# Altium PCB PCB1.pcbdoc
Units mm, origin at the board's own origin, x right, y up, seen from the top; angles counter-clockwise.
Board outline 105.66 x 88.01 mm, 2 copper layers (Top Layer, Bottom Layer), stack 1.58 mm thick; 25 components, 28 nets, 102 pads, 0 vias.
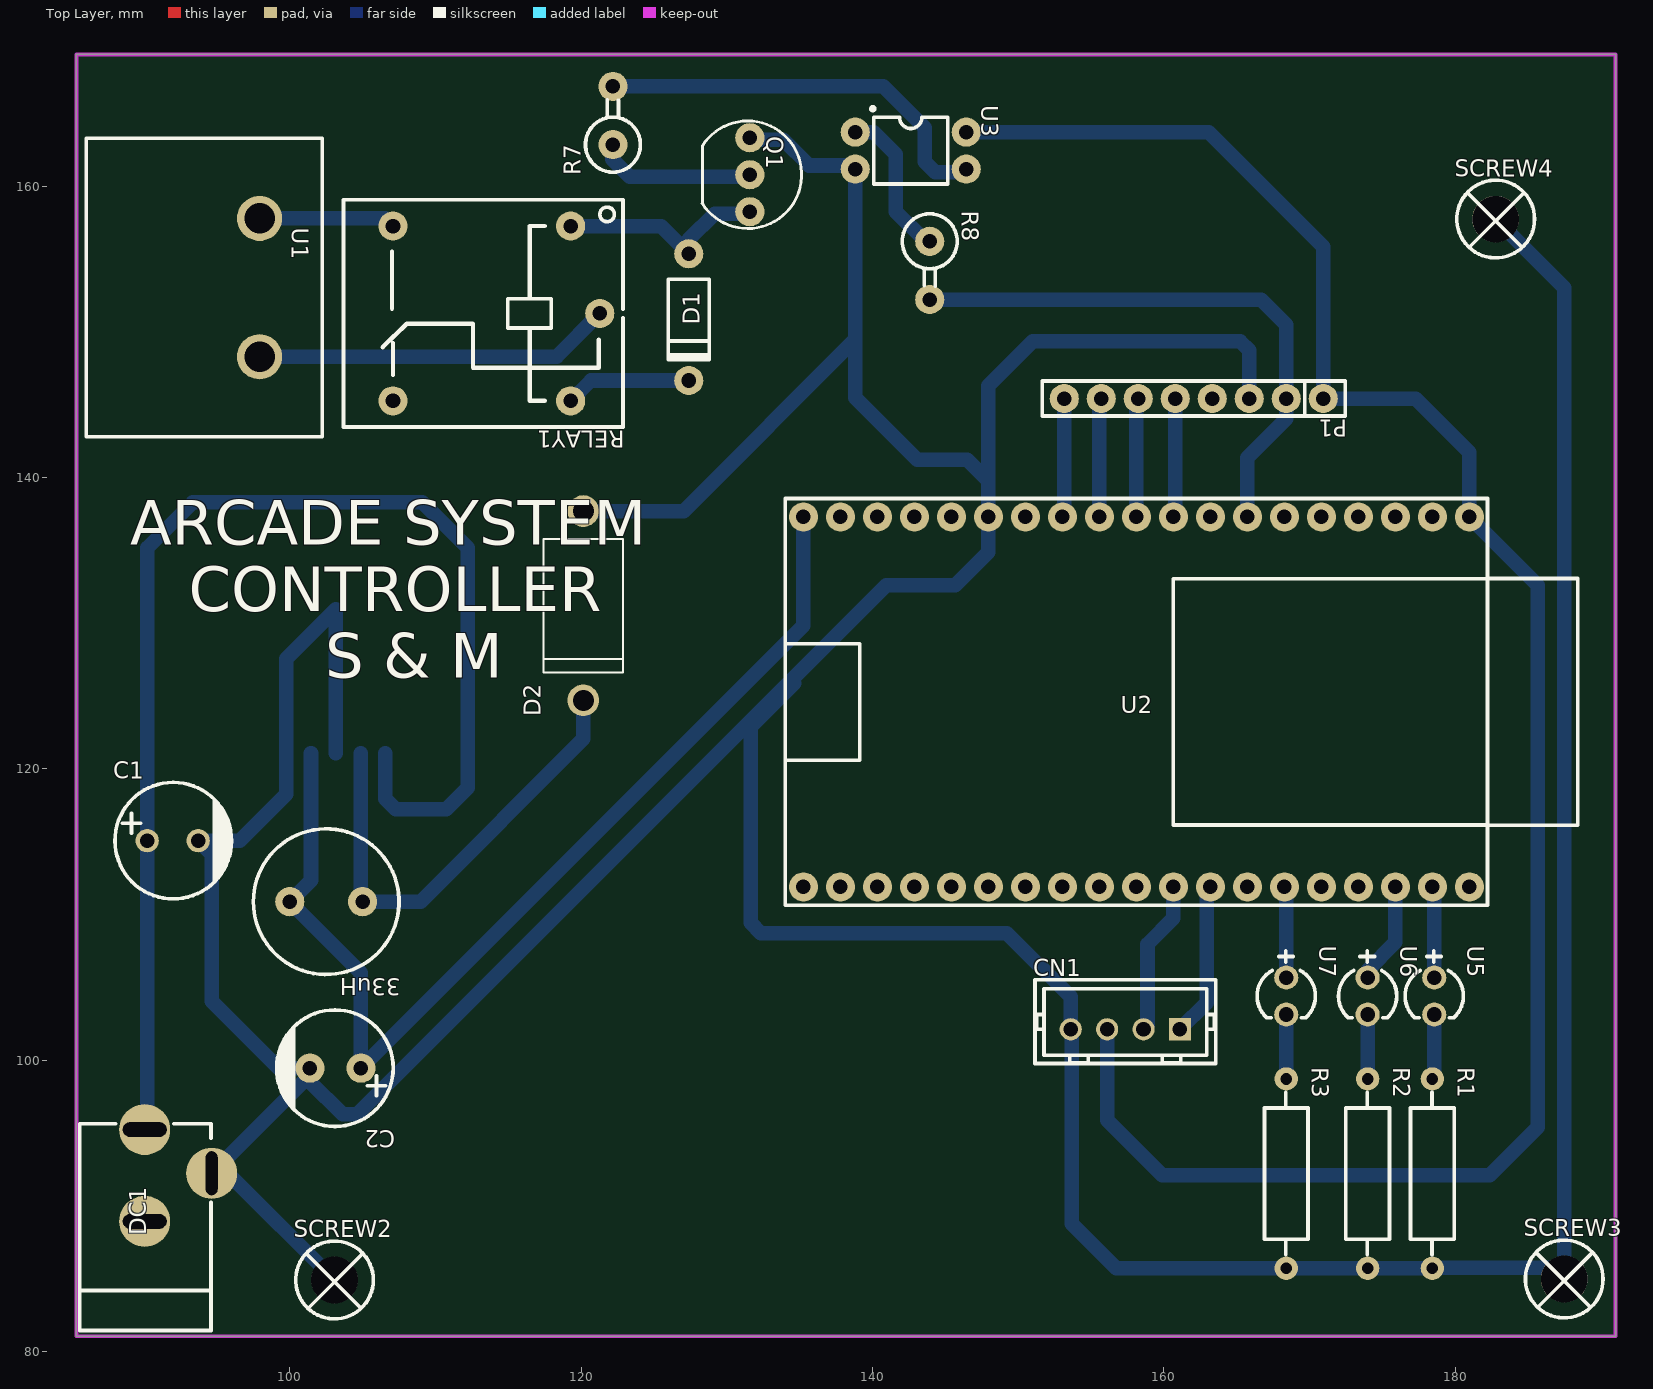
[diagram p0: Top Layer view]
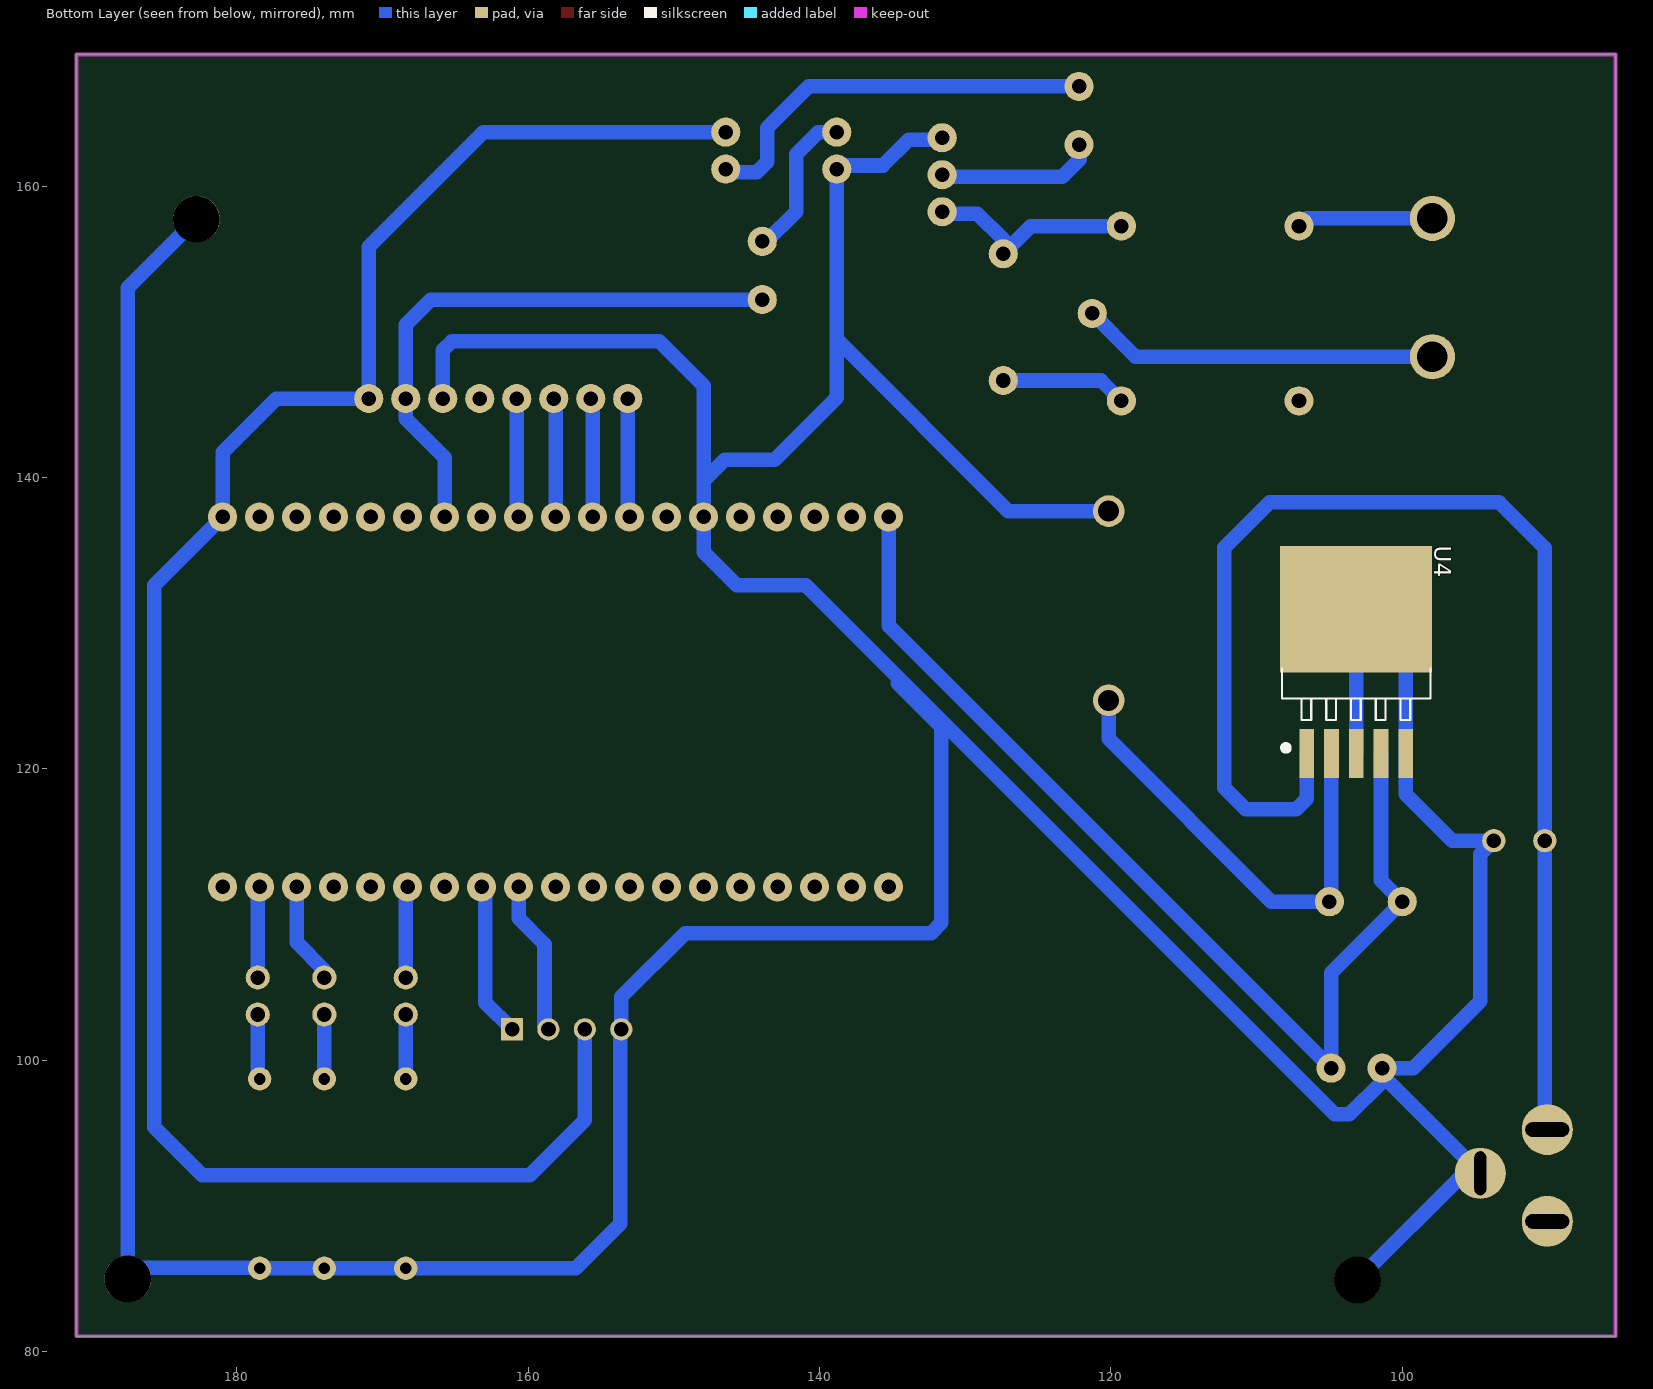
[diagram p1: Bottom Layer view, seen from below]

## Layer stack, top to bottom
Top Solder Mask Layer: solder mask 0.01, Dk 3.3
Top Layer: signal copper 0.035
Dielectric1: surface 1.51, FR4, Dk 4.5
Bottom Layer: signal copper 0.035
Bottom Solder Mask Layer: solder mask 0.01, Dk 3.3

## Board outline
85.344,169.037 85.344,81.026 191.008,81.026 191.008,169.037

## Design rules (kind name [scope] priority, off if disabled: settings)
BoardOutlineClearance copperThickness1oz [All] p0: genericclearance=0.254 ignorepadtopadclearanceinfootprint=FALSE except(0: Arc-SplitContinuation Track-SplitContinuation SMDPad-SplitContinuation THPad-SplitContinuation Via-SplitContinuation Fill-SplitContinuation Poly-SplitContinuation Region-SplitContinuation Text-SplitContinuation)
BoardOutlineClearance copperThickness2oz [All] p0: genericclearance=0.254 ignorepadtopadclearanceinfootprint=FALSE except(0: Arc-SplitContinuation Track-SplitContinuation SMDPad-SplitContinuation THPad-SplitContinuation Via-SplitContinuation Fill-SplitContinuation Poly-SplitContinuation Region-SplitContinuation Text-SplitContinuation)
BoardOutlineClearance Plane_innerPlane [All] p0: genericclearance=0.254 ignorepadtopadclearanceinfootprint=FALSE except(0: Arc-SplitContinuation Track-SplitContinuation SMDPad-SplitContinuation THPad-SplitContinuation Via-SplitContinuation Fill-SplitContinuation Poly-SplitContinuation Region-SplitContinuation Text-SplitContinuation)
BoardOutlineClearance Copper_copperRegion [All] p0: genericclearance=0.254 ignorepadtopadclearanceinfootprint=FALSE except(0: Arc-SplitContinuation Track-SplitContinuation SMDPad-SplitContinuation THPad-SplitContinuation Via-SplitContinuation Fill-SplitContinuation Poly-SplitContinuation Region-SplitContinuation Text-SplitContinuation)
BoardOutlineClearance otherClearance [All] p0: genericclearance=0.254 ignorepadtopadclearanceinfootprint=FALSE except(0: Arc-SplitContinuation Track-SplitContinuation SMDPad-SplitContinuation THPad-SplitContinuation Via-SplitContinuation Fill-SplitContinuation Poly-SplitContinuation Region-SplitContinuation Text-SplitContinuation)
Clearance copperThickness1oz [All] p1: gap=0.178 ignorepadtopadclearanceinfootprint=FALSE
Clearance copperThickness2oz [All] p1: gap=0.178 ignorepadtopadclearanceinfootprint=FALSE
Clearance Plane_innerPlane [All] p1: gap=0.178 ignorepadtopadclearanceinfootprint=FALSE
Clearance Copper_copperRegion [All] p1: gap=0.178 ignorepadtopadclearanceinfootprint=FALSE
Clearance otherClearance [All] p1: gap=0.178 ignorepadtopadclearanceinfootprint=FALSE
DiffPairsRouting differentialPair [All] p1: maxuncoupledlength=10 minlimit=6 maxlimit=Infinity mostfreqgap=6 toplayer_minwidth=5 toplayer_prefwidth=10 toplayer_maxwidth=100 bottomlayer_minwidth=5 bottomlayer_prefwidth=10 bottomlayer_maxwidth=100
PasteMaskExpansion pasteMaskExpansion [All] p1: expansion=0
PlaneConnect innerPlane [All] p1: planeconnectstyle=Relief reliefexpansion=0.508 reliefentries=4 reliefconductorwidth=0.254 reliefairgap=0.254
PolygonConnect copperRegion [All] p1: connectstyle=Relief reliefentries=4 reliefconductorwidth=10 polygonreliefangle="90 Angle" airgapwidth=10
RoutingVias viaSize [All] p1: viastyle="Through Hole" holewidth=12.0078 minholewidth=11.811 maxholewidth=248.0314 width=12.0078 minwidth=11.811 maxwidth=248.0314
SolderMaskExpansion solderMaskExpansion [IsVia] p1: useseparateexpansions=TRUE expansion=-1000 expansionbottom=-1000
SolderMaskExpansion solderMaskExpansion [All] p2: useseparateexpansions=TRUE expansion=2 expansionbottom=2
Width copperThickness1oz [All] p1: maxlimit=100 minlimit=5 preferedwidth=31
Width copperThickness2oz [All] p1: maxlimit=100 minlimit=8 preferedwidth=10

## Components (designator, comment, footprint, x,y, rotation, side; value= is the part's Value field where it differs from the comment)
33uH "-" IND-TH_BD10.0-P5.00-D0.7 102.489,110.871 r180 top
C1 "220uF" CAP-TH_BD8.0-P3.50-D0.6-FD#1 91.948,115.062 r0 top
C2 "220uF" CAP-TH_BD8.0-P3.50-D0.6-FD#2 103.124,99.441 r180 top
CN1 "B4B-XH-A-R(LF)(SN)" CONN-TH_4P-P2.50_JST_B4B-XH-A-M 157.353,102.108 r0 top
D1 "1N4007" DO-41_BD2.4-L4.7-P8.70-D0.6-RD 127.381,151.003 r90 top
D2 "1N5824" DO-201AD_BD5.3-L9.0-P13.00-D1.3-RD 120.142,131.191 r90 top
DC1 "DC-005 2.0" DC-IN-TH_DC-005-5.5-2.0 92.329,92.075 r90 top
P1 "2.54-1*8P母环保" HDR-TH_8P-P2.54-V-F 162.052,145.415 r180 top
Q1 "2N2222A" TO-92-3_L5.1-W4.1-P1.27-L-1 130.175,160.782 r270 top
R1 "AXIAL0.5 1K/0.5W/1%" RES-TH_BD3.0-L9.0-P13.0-D0.6 178.435,92.202 r270 top
R2 "AXIAL0.5 1K/0.5W/1%" RES-TH_BD3.0-L9.0-P13.0-D0.6 173.99,92.202 r270 top
R3 "AXIAL0.5 1K/0.5W/1%" RES-TH_BD3.0-L9.0-P13.0-D0.6 168.402,92.202 r270 top
R7 "220Ω" RES-TH_BD3.5-P4.00-D0.7 122.174,164.846 r90 top
R8 "220Ω" RES-TH_BD3.5-P4.00-D0.7 143.923,154.21 r270 top
RELAY1 "" RELAY-TH_SRD-XXVDC-XL-C 114.173,151.257 r180 top
SCREW2 "" Screw-Hole-M3 103.124,84.836 r0 top
SCREW3 "" Screw-Hole-M3 187.55,84.903 r0 top
SCREW4 "" Screw-Hole-M3 182.843,157.674 r0 top
U1 "DBT50G-9.5-2P-BK-P OGC" CONN-TH_2P-P9.50_DBT50G-9.5-2P 97.917,153.035 r270 top
U2 "ESP32-DEVKITC-VE" BULETM-SMD_ESP32-DEVKITC 158.115,124.587 r180 top
U3 "PC817C" DIP-4_L6.5-W4.6-P2.54-LS7.6-BL 142.621,162.433 r270 top
U4 "LM2596S-12" TO-263-5_L10.1-W8.7-P1.70-LS14.4-BR 103.147,126.005 r270 bottom
U5 "LED" LED-TH_BD4.0-P2.54-FD_RED 178.562,104.394 r270 top
U6 "LED" LED-TH_BD4.0-P2.54-FD_RED 173.99,104.394 r270 top
U7 "LED" LED-TH_BD4.0-P2.54-FD_RED 168.402,104.394 r270 top

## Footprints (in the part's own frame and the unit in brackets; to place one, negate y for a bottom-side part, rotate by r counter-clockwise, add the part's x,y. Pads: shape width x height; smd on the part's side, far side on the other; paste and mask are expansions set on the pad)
BULETM-SMD_ESP32-DEVKITC [mm]
  round 2 hole 1 paste+0 mask+0.05: 1(-22.86,-12.7) 2(-20.32,-12.7) 3(-17.78,-12.7) 4(-15.24,-12.7) 5(-12.7,-12.7) 6(-10.16,-12.7) 7(-7.62,-12.7) 8(-5.08,-12.7) 9(-2.54,-12.7) 10(0,-12.7) 11(2.54,-12.7) 12(5.08,-12.7) 13(7.62,-12.7) 14(10.16,-12.7) 15(12.7,-12.7) 16(15.24,-12.7) 17(17.78,-12.7) 18(20.32,-12.7) 19(22.86,-12.7) 20(-22.86,12.7) 21(-20.32,12.7) 22(-17.78,12.7) 23(-15.24,12.7) 24(-12.7,12.7) 25(-10.16,12.7) 26(-7.62,12.7) 27(-5.08,12.7) 28(-2.54,12.7) 29(0,12.7) 30(2.54,12.7) 31(5.08,12.7) 32(7.62,12.7) 33(10.16,12.7) 34(12.7,12.7) 35(15.24,12.7) 36(17.78,12.7) 37(20.32,12.7) 38(22.86,12.7)
  silkscreen extent -30.3,-13.97 24.1,13.97
CAP-TH_BD8.0-P3.50-D0.6-FD#1 [mm]
  round 1.6 hole 1: 1(-1.75,0) 2(1.75,0)
  silkscreen extent -3.96,-4 4.04,4
CAP-TH_BD8.0-P3.50-D0.6-FD#2 [mm]
  round 2 hole 1: 1(-1.75,0) 2(1.75,0)
  silkscreen extent -3.96,-4 4.04,4
CONN-TH_2P-P9.50_DBT50G-9.5-2P [mm]
  round 3.1 hole 2.1 paste+0 mask+0.05: 1(-4.75,0) 2(4.75,0)
  silkscreen extent -10.25,-11.9 10.25,4.3
CONN-TH_4P-P2.50_JST_B4B-XH-A-M [mil]
  rect 60x60 hole 39.37 paste+0 mask+1.97: 1(147.64,0)
  round 60 hole 39.37 paste+0 mask+1.97: 2(49.21,0) 3(-49.22,0) 4(-147.65,0)
  silkscreen extent -244,-93 244,134
DC-IN-TH_DC-005-5.5-2.0 [mm]
  round 3.5 hole 0.8 slot 3 at 0 deg copper offset 0,0: 2(0.15,-2.3)
  round 3.5 hole 1 slot 3 at 90 deg: 3(-3.15,2.3) 4(3.15,2.3)
  silkscreen extent -10.65,-2.26 3.55,6.75
DIP-4_L6.5-W4.6-P2.54-LS7.6-BL [mm]
  round 2 hole 1: 1(-1.27,-3.81) 2(1.27,-3.81) 3(1.27,3.81) 4(-1.27,3.81)
  silkscreen extent -3,-2.73 2.29,2.54
DO-41_BD2.4-L4.7-P8.70-D0.6-RD [mm]
  round 2 hole 1: 1(-4.35,0) 2(4.35,0)
  silkscreen extent -2.92,-1.4 2.6,1.4
DO-201AD_BD5.3-L9.0-P13.00-D1.3-RD [mm]
  round 2.175 hole 1.45: 1(-6.5,0) 2(6.5,0)
  silkscreen extent -4.58,-2.73 4.58,2.73
HDR-TH_8P-P2.54-V-F [mm]
  round 2 hole 1: 1(-8.89,0) 2(-6.35,0) 3(-3.81,0) 4(-1.27,0) 5(1.27,0) 6(3.81,0) 7(6.35,0) 8(8.89,0)
  silkscreen extent -10.4,-1.2 10.4,1.2
IND-TH_BD10.0-P5.00-D0.7 [mm]
  round 2 hole 1: 1(-2.5,0) 2(2.5,0)
  silkscreen extent -5,-5 5,5
LED-TH_BD4.0-P2.54-FD_RED [mil]
  round 65 hole 39.37: 1(-50,0) 2(50,0)
  silkscreen extent -122,-79 59,79
RELAY-TH_SRD-XXVDC-XL-C [mm]
  round 2 hole 1: 1(-5.1,-6) 2(7.1,-5.999) 3(7.1,5.999) 4(-5.1,6) 5(-7.1,0)
  silkscreen extent -8.7,-7.8 10.5,7.8
RES-TH_BD3.0-L9.0-P13.0-D0.6 [mm]
  round 1.6 hole 0.8: 1(-6.5,0) 2(6.5,0)
  silkscreen extent -5.58,-1.5 5.58,1.5
RES-TH_BD3.5-P4.00-D0.7 [mm]
  round 2 hole 1: 1(-2,0) 2(2,0)
  silkscreen extent -3.89,-1.88 1.08,1.88
Screw-Hole-M3 [mil]
  round 126 hole 126 paste+0 mask+4: 1(-2.5,2.5)
  silkscreen extent -107,-102 102,107
TO-92-3_L5.1-W4.1-P1.27-L-1 [mm]
  round 2 hole 1: 1(-2.54,1.397) 2(0,1.397) 3(2.54,1.397)
  silkscreen extent -3.69,-1.87 3.69,4.95
TO-263-5_L10.1-W8.7-P1.70-LS14.4-BR [mm]
  rect 3.359x1.02 smd: 1(4.948,-3.4) 2(4.948,-1.7) 3(4.948,0) 4(4.948,1.7) 5(4.948,3.4)
  rect 8.7x10.431 smd: 6(-4.948,0)
  silkscreen extent -0.88,-5.09 4.77,5.09

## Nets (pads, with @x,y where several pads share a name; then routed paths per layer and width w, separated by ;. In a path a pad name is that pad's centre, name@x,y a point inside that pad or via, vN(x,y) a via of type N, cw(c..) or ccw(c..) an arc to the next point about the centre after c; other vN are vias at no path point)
5V: 33uH.2 C2.1 U2.19 U4.4 | length 74.7
  Bottom Layer w1: U4.4 101.447,112.329 33uH.2 104.874,105.986 C2.1 135.255,129.822 U2.19
12V: C1.1 DC1.4 U4.1 | length 90.8
  Bottom Layer w1: DC1.4@90.029,95.225 90.198,95.394 C1.1 90.198,135.156 93.345,138.303 109.093,138.303 112.213,135.183 112.213,118.69 110.744,117.221 107.254,117.221 106.547,117.928 U4.1
$1N2126: R8.1 U3.1 | length 10.5
  Bottom Layer w1: U3.1 140.081,163.703 141.605,162.179 141.605,158.242 143.637,156.21 R8.1
$1N2211: R7.2 U3.3 | length 28.1
  Bottom Layer w1: R7.2 140.748,166.846 143.582,164.012 143.582,161.671 144.289,160.964 146.232,160.964 U3.3
$1N2213: Q1.2 R7.1 | length 11
  Bottom Layer w1: R7.1 122.12,162.792 122.12,161.852 123.317,160.655 131.445,160.655 Q1.2
$1N2266: D1.2 Q1.3 RELAY1.1 | length 14.9
  Bottom Layer w1: RELAY1.1 125.477,157.257 D1.2 127.381,156.337 129.159,158.115 131.445,158.115 Q1.3
$1N2299: D1.1 RELAY1.4 | length 8.7
  Bottom Layer w1: RELAY1.4 120.669,146.653 D1.1
$1N2391: RELAY1.5 U1.2 | length 24.6
  Bottom Layer w1: U1.2 118.301,148.285 RELAY1.5
$1N2396: RELAY1.2 U1.1 | length 9.4
  Bottom Layer w1: U1.1 106.544,157.785 RELAY1.2
$1N2759: U2.20
$1N2804: R1.1 U5.2 | length 4.5
  Bottom Layer w1: R1.1 178.562,98.829 U5.2
$1N2805: R2.1 U6.2 | length 4.4
  Bottom Layer w1: R2.1 U6.2
$1N2806: R3.1 U7.2 | length 4.4
  Bottom Layer w1: R3.1 U7.2
GAME: U2.25 U7.1 | length 6.3
  Bottom Layer w1: U2.25 168.402,111.76 U7.1
GND: C1.2 C2.2 CN1.4 D2.2 DC1.2 P1.3 Q1.1 R1.2 R2.2 R3.2 SCREW2.1 SCREW3.1 SCREW4.1 U2.14 U3.2 U4.3 U4.5 U4.6 | length 397.4
  Bottom Layer w1: SCREW2.1 95.735,92.225 94.629,92.225 C2.2@101.374,98.97 ; U4.3 U4.6 99.747,127.553 U4.5 99.747,118.262 96.547,115.062 C1.2 94.629,114.131 94.629,104.036 99.224,99.441 C2.2 C2.2@101.374,98.97 ; D2.2 127.023,137.691 138.811,149.479 ; Q1.1 131.699,163.195 133.858,163.195 135.636,161.417 138.557,161.417 U3.2 138.811,149.479 ; 134.62,125.857 131.627,122.864 131.627,109.419 132.334,108.712 149.225,108.712 153.603,104.334 CN1.4 153.67,102.041 153.67,88.75 156.718,85.702 R3.2 R2.2 R1.2 178.458,85.725 186.729,85.725 SCREW3.1 187.487,153.031 SCREW4.1 ; P1.3 165.862,148.717 165.227,149.352 151.003,149.352 147.955,146.304 147.955,139.772 ; C2.2@101.374,98.97 101.374,98.524 103.632,96.266 104.632,96.266 140.954,132.588 145.669,132.588 147.955,134.874 U2.14 147.955,139.772 ; 138.811,149.479 138.811,145.475 143.062,141.224 146.503,141.224 147.955,139.772
MISO: P1.5 U2.9 | length 8.2
  Bottom Layer w1: U2.9 160.782,137.414 P1.5
MOSI: P1.6 U2.10 | length 8.2
  Bottom Layer w1: U2.10 158.115,145.288 P1.6
MQTT: U2.22 U6.1 | length 6.5
  Bottom Layer w1: U6.1@173.99,106.172 175.895,108.077 U2.22
OUTPUT: 33uH.1 D2.1 U4.2 | length 32.7
  Bottom Layer w1: U4.2 104.847,111.013 33uH.1 108.966,110.871 120.142,122.047 D2.1
RELAY: P1.2 R8.2 U2.7 | length 39.5
  Bottom Layer w1: R8.2 166.687,152.21 168.402,150.495 P1.2 168.402,144.018 165.735,141.351 U2.7
SCL_lcd: CN1.1 U2.27
SCL_LCD:  | length 10.5
  Bottom Layer w1: 161.103,102.108 162.941,103.946 162.941,111.887
SCLK: P1.7 U2.11 | length 8.2
  Bottom Layer w1: U2.11 155.575,145.288 P1.7
SDA: P1.8 U2.12 | length 8.2
  Bottom Layer w1: U2.12 153.162,137.414 P1.8
SDA_lcd: CN1.2 U2.28 | length 0.4
  Bottom Layer w1: CN1.2 CN1.2@158.877,102.382
SDA_LCD:  | length 10.2
  Bottom Layer w1: 158.877,102.382 158.877,107.95 160.655,109.728 160.655,111.887
VCC: CN1.3 P1.1 U2.1 U3.4 | length 136.8
  Bottom Layer w1: U3.4 163.068,163.703 170.942,155.829 P1.1 177.292,145.415 180.975,141.732 U2.1 185.674,132.588 185.674,95.377 182.372,92.075 159.893,92.075 156.103,95.865 CN1.3
WIFI: U2.21 U5.1 | length 5.5
  Bottom Layer w1: U2.21 178.562,111.76 U5.1@178.562,106.426
pads on no net: DC1.3 P1.4 RELAY1.3 U2.2 U2.3 U2.4 U2.5 U2.6 U2.8 U2.13 U2.15 U2.16 U2.17 U2.18 U2.23 U2.24 U2.26 U2.29 U2.30 U2.31 U2.32 U2.33 U2.34 U2.35 U2.36 U2.37 U2.38

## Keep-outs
Board Outline Layer:
  the board outline again, w0.254

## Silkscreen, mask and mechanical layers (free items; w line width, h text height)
Top Silkscreen Layer:
  text "ARCADE SYSTEM /    CONTROLLER  /           S & M" at 89.027,126.238 h3.05
Top Solder Mask Layer:
  region: 185.547,168.783 185.547,163.783 190.547,163.783 190.547,168.783
Bottom Solder Mask Layer:
  text "hight: 1.5" at 85.598,83.312 h3.05

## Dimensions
182.372,114.596 to 133.858,114.596 on Document Layer
191.008,76.2 to 85.344,76.2 on Document Layer
151.652,147.447 to 141.605,147.447 on Document Layer
172.466,144.018 to 172.466,205.486 on Document Layer
205.232,92.964 to 205.232,205.486 on Document Layer
85.576,88.392 to 94.576,88.392 on Document Layer
83.058,141.732 to 83.058,93.091 on Document Layer
81.026,163.322 to 81.026,141.605 on Document Layer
